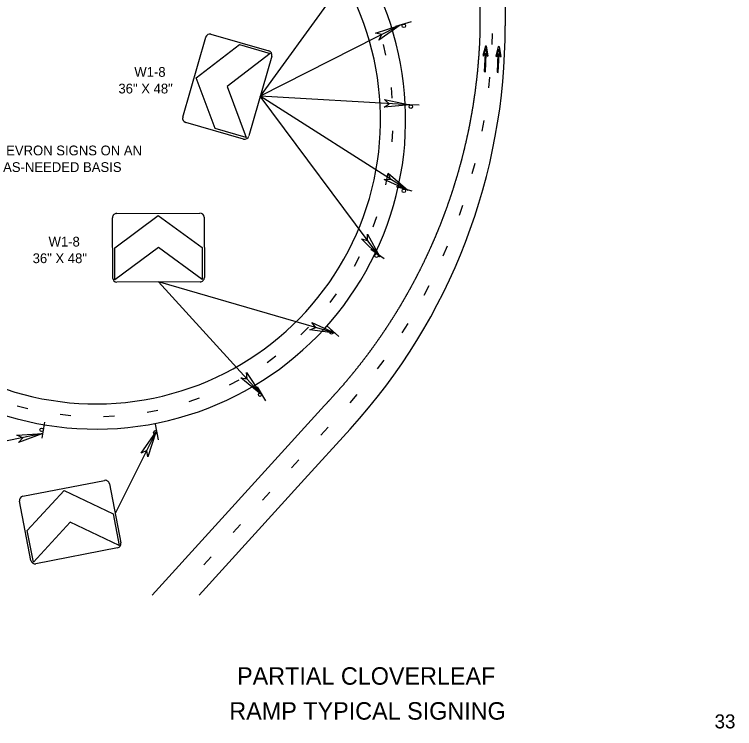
# Model space of a CAD drawing. Extents: x 582908 to 586039, y 1530940 to 1532988.
# Drawn here: x 585008 to 586039, y 1530991 to 1532013 of the extents above; entities that cross this region are included whole.
import ezdxf

# ---------------------------------------------------------------- set-up
doc = ezdxf.new("R2010")
doc.units = 0
for name, color, linetype in [('DirArrowsPavt', 7, 'Continuous'), ('LeaderLine_dp', 7, 'Continuous'), ('PMStripe6W', 7, 'Continuous'), ('PMStripe6W(10-30)', 7, 'Continuous'), ('PMStripe6Y', 7, 'Continuous'), ('SignPanel', 7, 'Continuous'), ('SignSupport', 7, 'Continuous'), ('TextLabel', 7, 'Continuous'), ('TextMisc', 7, 'Continuous'), ('TextShtNo', 7, 'Continuous')]:
    doc.layers.add(name, color=color, linetype=linetype)

# ---------------------------------------------------------------- blocks, each defined once
blk = doc.blocks.new('ArrTermPnt')
at = {"layer": 'LeaderLine_dp'}
for p, q in [((-0.1, 0), (-0.12, 0.02)), ((-0.12, 0.02), (0, 0)), ((0, 0), (-0.12, -0.02)), ((-0.12, -0.02), (-0.1, 0))]:
    blk.add_line(p, q, dxfattribs=at)

msp = doc.modelspace()

# ---------------------------------------------------------------- linework, layer by layer
at = {"layer": 'DirArrowsPavt'}
for p, q in [((585682.8, 1531967.4), (585679.1, 1531953.9)), ((585684.4, 1531967.4), (585682.8, 1531967.4)), ((585686.9, 1531953.5), (585684.4, 1531967.4)), ((585680.6, 1531953.5), (585683.5, 1531963.9)), ((585683.5, 1531963.9), (585685.3, 1531953.2)), ((585701.2, 1531966.6), (585697.5, 1531953)), ((585699, 1531952.6), (585701.9, 1531963)), ((585702.8, 1531966.5), (585701.2, 1531966.6)), ((585701.9, 1531963), (585703.7, 1531952.4)), ((585705.3, 1531952.7), (585702.8, 1531966.5)), ((585679.1, 1531953.9), (585680.6, 1531953.5)), ((585682.3, 1531956.5), (585681.2, 1531930.8)), ((585683.9, 1531956.4), (585682.3, 1531956.5)), ((585682.7, 1531930.7), (585683.9, 1531956.4)), ((585685.3, 1531953.2), (585686.9, 1531953.5)), ((585697.5, 1531953), (585699, 1531952.6)), ((585700.7, 1531955.7), (585699.6, 1531929.9)), ((585702.3, 1531955.6), (585700.7, 1531955.7)), ((585701.1, 1531929.8), (585702.3, 1531955.6)), ((585703.7, 1531952.4), (585705.3, 1531952.7)), ((585681.2, 1531930.8), (585682.7, 1531930.7)), ((585699.6, 1531929.9), (585701.1, 1531929.8))]:
    msp.add_line(p, q, dxfattribs=at)
at = {"layer": 'LeaderLine_dp'}
for p, q in [((585513.2, 1532106.3), (585360.5, 1531895.8)), ((585560.5, 1531997.4), (585360.5, 1531895.8)), ((585525.4, 1531985.7), (585560.5, 1531997.4)), ((585560.5, 1531997.4), (585530.3, 1531975.9)), ((585534.4, 1531984.1), (585525.4, 1531985.7)), ((585530.3, 1531975.9), (585534.4, 1531984.1)), ((585531.5, 1531665.6), (585360.5, 1531895.8)), ((585574.4, 1531883.1), (585360.5, 1531895.8)), ((585571.5, 1531761.3), (585360.5, 1531895.8)), ((585537.6, 1531879.8), (585545.2, 1531884.9)), ((585545.2, 1531884.9), (585538.2, 1531890.8)), ((585538.2, 1531890.8), (585574.4, 1531883.1)), ((585574.4, 1531883.1), (585537.6, 1531879.8)), ((585546.8, 1531777.1), (585543.6, 1531785.6)), ((585543.6, 1531785.6), (585571.5, 1531761.3)), ((585537.7, 1531776.4), (585546.8, 1531777.1)), ((585571.5, 1531761.3), (585537.7, 1531776.4)), ((585531.5, 1531665.6), (585505.3, 1531691.7)), ((585505.3, 1531691.7), (585514.1, 1531689.1)), ((585514.1, 1531689.1), (585514.1, 1531698.3)), ((585514.1, 1531698.3), (585531.5, 1531665.6)), ((585467.9, 1531556.3), (585214.8, 1531629.8)), ((585361.4, 1531469.3), (585214.8, 1531629.8)), ((585439.8, 1531564.4), (585434.3, 1531571.7)), ((585434.3, 1531571.7), (585467.9, 1531556.3)), ((585431.3, 1531561.2), (585439.8, 1531564.4)), ((585467.9, 1531556.3), (585431.3, 1531561.2)), ((585341.7, 1531490.9), (585340.8, 1531500)), ((585340.8, 1531500), (585361.4, 1531469.3)), ((585361.4, 1531469.3), (585332.7, 1531492.6)), ((585332.7, 1531492.6), (585341.7, 1531490.9)), ((585049.1, 1531412.7), (584837.2, 1531369)), ((585012.2, 1531410.7), (585049.1, 1531412.7)), ((585020.5, 1531406.8), (585012.2, 1531410.7)), ((585049.1, 1531412.7), (585014.4, 1531400)), ((585211.1, 1531414.7), (585152.7, 1531298.6)), ((585189.8, 1531384.5), (585211.1, 1531414.7)), ((585211.1, 1531414.7), (585199.6, 1531379.6)), ((585014.4, 1531400), (585020.5, 1531406.8)), ((585198, 1531388.6), (585189.8, 1531384.5)), ((585199.6, 1531379.6), (585198, 1531388.6))]:
    msp.add_line(p, q, dxfattribs=at)
at = {"layer": 'PMStripe6W'}
for p, q in [((585710.3, 1532156.5), (585711, 1531996.2)), ((585489.3, 1531419.3), (585423.8, 1531347.3)), ((585423.8, 1531347.3), (585273.2, 1531181.7))]:
    msp.add_line(p, q, dxfattribs=at)
for centre, radius, start, end in [((585125.6, 1531862.2), 407, 225.0711, 46.1803), ((584859.2, 1531992.4), 851.8, 317.7128, 0.254)]:
    msp.add_arc(centre, radius, start, end, dxfattribs=at)
at = {"layer": 'PMStripe6W(10-30)'}
for p, q in [((585692.3, 1531969.8), (585692.8, 1531985.4)), ((585540.4, 1531954.5), (585536.8, 1531969.7)), ((585687.5, 1531907.5), (585689.2, 1531923)), ((585549.5, 1531892.8), (585548.1, 1531908.3)), ((585678.1, 1531845.7), (585680.9, 1531861.1)), ((585549.4, 1531830.3), (585550.3, 1531845.9)), ((585664, 1531784.8), (585668, 1531799.9)), ((585540.1, 1531768.6), (585543.3, 1531783.9)), ((585645.5, 1531725.2), (585650.5, 1531739.9)), ((585521.9, 1531708.8), (585527.3, 1531723.5)), ((585622.5, 1531667.1), (585628.6, 1531681.4)), ((585495.2, 1531652.4), (585502.6, 1531666.1)), ((585595.2, 1531610.9), (585602.4, 1531624.7)), ((585460.4, 1531600.5), (585469.8, 1531613)), ((585418.5, 1531554.3), (585429.6, 1531565.2)), ((585563.7, 1531556.8), (585572, 1531570.1)), ((585370.2, 1531514.7), (585382.8, 1531523.9)), ((585528.3, 1531505.3), (585537.6, 1531518)), ((585316.6, 1531482.6), (585330.4, 1531489.9)), ((585258.9, 1531458.7), (585273.7, 1531463.9)), ((585489.2, 1531456.6), (585499.3, 1531468.5)), ((585012.6, 1531452.5), (585027.7, 1531448.7)), ((585198.4, 1531443.5), (585213.7, 1531446.5)), ((585073.8, 1531440.4), (585089.4, 1531438.8)), ((585136.2, 1531437.4), (585151.8, 1531438)), ((585447.3, 1531410.3), (585457.8, 1531421.8)), ((585405.4, 1531363.9), (585415.9, 1531375.4)), ((585363.5, 1531317.5), (585374.1, 1531329)), ((585321.7, 1531271.1), (585332.2, 1531282.7)), ((585279.8, 1531224.7), (585290.3, 1531236.3))]:
    msp.add_line(p, q, dxfattribs=at)
at = {"layer": 'PMStripe6Y'}
for p, q in [((585673.5, 1532343.3), (585675, 1531996.1)), ((585452.3, 1531452.9), (585205.7, 1531181.7))]:
    msp.add_line(p, q, dxfattribs=at)
msp.add_arc((585125.6, 1531862.2), 443, 225.021, 46.2304, dxfattribs=at)
for points in [[(585675, 1531996), (585675, 1531994.7), (585675, 1531993.3), (585675, 1531992), (585674.9, 1531990.6), (585674.9, 1531989.2), (585674.9, 1531987.9), (585674.8, 1531986.5), (585674.8, 1531985.1), (585674.7, 1531983.8), (585674.7, 1531982.4), (585674.6, 1531981), (585674.6, 1531979.7), (585674.5, 1531978.3), (585674.5, 1531977), (585674.4, 1531975.6), (585674.3, 1531974.2), (585674.3, 1531972.9), (585674.2, 1531971.5), (585674.1, 1531970.1), (585674.1, 1531968.8), (585674, 1531967.4), (585673.9, 1531966.1), (585673.9, 1531964.7), (585673.8, 1531963.3), (585673.7, 1531962), (585673.6, 1531960.6), (585673.5, 1531959.3), (585673.4, 1531957.9), (585673.3, 1531956.5), (585673.3, 1531955.2), (585673.2, 1531953.8), (585673.1, 1531952.5), (585673, 1531951.1), (585672.9, 1531949.7), (585672.8, 1531948.4), (585672.6, 1531947), (585672.5, 1531945.7), (585672.4, 1531944.3), (585672.3, 1531942.9), (585672.2, 1531941.6), (585672.1, 1531940.2), (585672, 1531938.9), (585671.8, 1531937.5), (585671.7, 1531936.2), (585671.6, 1531934.8), (585671.5, 1531933.4), (585671.3, 1531932.1), (585671.2, 1531930.7), (585671.1, 1531929.4), (585670.9, 1531928), (585670.8, 1531926.7), (585670.6, 1531925.3), (585670.5, 1531924), (585670.3, 1531922.6), (585670.2, 1531921.2), (585670, 1531919.9), (585669.9, 1531918.5), (585669.7, 1531917.2), (585669.6, 1531915.8), (585669.4, 1531914.5), (585669.2, 1531913.1), (585669.1, 1531911.8), (585668.9, 1531910.4), (585668.7, 1531909.1), (585668.6, 1531907.7), (585668.4, 1531906.4), (585668.2, 1531905), (585668, 1531903.7), (585667.9, 1531902.3), (585667.7, 1531901), (585667.5, 1531899.6), (585667.3, 1531898.3), (585667.1, 1531896.9), (585666.9, 1531895.6)], [(585666.9, 1531895.6), (585666.7, 1531894.2), (585666.5, 1531892.9), (585666.3, 1531891.6), (585666.1, 1531890.2), (585665.9, 1531888.9), (585665.7, 1531887.5), (585665.5, 1531886.2), (585665.3, 1531884.8), (585665.1, 1531883.5), (585664.9, 1531882.1), (585664.7, 1531880.8), (585664.4, 1531879.5), (585664.2, 1531878.1), (585664, 1531876.8), (585663.8, 1531875.4), (585663.5, 1531874.1), (585663.3, 1531872.7), (585663.1, 1531871.4), (585662.8, 1531870.1), (585662.6, 1531868.7), (585662.4, 1531867.4), (585662.1, 1531866.1), (585661.9, 1531864.7), (585661.6, 1531863.4), (585661.4, 1531862), (585661.1, 1531860.7), (585660.9, 1531859.4), (585660.6, 1531858), (585660.4, 1531856.7), (585660.1, 1531855.4), (585659.9, 1531854), (585659.6, 1531852.7), (585659.3, 1531851.4), (585659.1, 1531850), (585658.8, 1531848.7), (585658.5, 1531847.4), (585658.2, 1531846), (585658, 1531844.7), (585657.7, 1531843.4), (585657.4, 1531842.1), (585657.1, 1531840.7), (585656.8, 1531839.4), (585656.5, 1531838.1), (585656.3, 1531836.7), (585656, 1531835.4), (585655.7, 1531834.1), (585655.4, 1531832.8), (585655.1, 1531831.4), (585654.8, 1531830.1), (585654.5, 1531828.8), (585654.2, 1531827.5), (585653.8, 1531826.1), (585653.5, 1531824.8), (585653.2, 1531823.5), (585652.9, 1531822.2), (585652.6, 1531820.9), (585652.3, 1531819.5), (585652, 1531818.2), (585651.6, 1531816.9), (585651.3, 1531815.6), (585651, 1531814.3), (585650.6, 1531812.9), (585650.3, 1531811.6), (585650, 1531810.3), (585649.6, 1531809), (585649.3, 1531807.7), (585649, 1531806.4), (585648.6, 1531805.1), (585648.3, 1531803.7), (585647.9, 1531802.4), (585647.6, 1531801.1), (585647.2, 1531799.8), (585646.9, 1531798.5), (585646.5, 1531797.2)], [(585646.5, 1531797.2), (585646.2, 1531795.9), (585645.8, 1531794.6), (585645.4, 1531793.3), (585645.1, 1531792), (585644.7, 1531790.7), (585644.3, 1531789.4), (585644, 1531788), (585643.6, 1531786.7), (585643.2, 1531785.4), (585642.8, 1531784.1), (585642.5, 1531782.8), (585642.1, 1531781.5), (585641.7, 1531780.2), (585641.3, 1531778.9), (585640.9, 1531777.6), (585640.5, 1531776.3), (585640.1, 1531775), (585639.7, 1531773.7), (585639.3, 1531772.4), (585638.9, 1531771.1), (585638.5, 1531769.9), (585638.1, 1531768.6), (585637.7, 1531767.3), (585637.3, 1531766), (585636.9, 1531764.7), (585636.5, 1531763.4), (585636.1, 1531762.1), (585635.7, 1531760.8), (585635.2, 1531759.5), (585634.8, 1531758.2), (585634.4, 1531756.9), (585634, 1531755.7), (585633.6, 1531754.4), (585633.1, 1531753.1), (585632.7, 1531751.8), (585632.3, 1531750.5), (585631.8, 1531749.2), (585631.4, 1531748), (585630.9, 1531746.7), (585630.5, 1531745.4), (585630.1, 1531744.1), (585629.6, 1531742.8), (585629.2, 1531741.6), (585628.7, 1531740.3), (585628.3, 1531739), (585627.8, 1531737.7), (585627.3, 1531736.4), (585626.9, 1531735.2), (585626.4, 1531733.9), (585626, 1531732.6), (585625.5, 1531731.4), (585625, 1531730.1), (585624.6, 1531728.8), (585624.1, 1531727.5), (585623.6, 1531726.3), (585623.1, 1531725), (585622.7, 1531723.7), (585622.2, 1531722.5), (585621.7, 1531721.2), (585621.2, 1531719.9), (585620.7, 1531718.7), (585620.2, 1531717.4), (585619.7, 1531716.2), (585619.3, 1531714.9), (585618.8, 1531713.6), (585618.3, 1531712.4), (585617.8, 1531711.1), (585617.3, 1531709.9), (585616.8, 1531708.6), (585616.3, 1531707.4), (585615.7, 1531706.1), (585615.2, 1531704.8), (585614.7, 1531703.6), (585614.2, 1531702.3)], [(585614.2, 1531702.3), (585613.7, 1531701.1), (585613.2, 1531699.8), (585612.7, 1531698.6), (585612.1, 1531697.3), (585611.6, 1531696.1), (585611.1, 1531694.9), (585610.6, 1531693.6), (585610, 1531692.4), (585609.5, 1531691.1), (585609, 1531689.9), (585608.4, 1531688.6), (585607.9, 1531687.4), (585607.3, 1531686.2), (585606.8, 1531684.9), (585606.3, 1531683.7), (585605.7, 1531682.4), (585605.2, 1531681.2), (585604.6, 1531680), (585604.1, 1531678.7), (585603.5, 1531677.5), (585602.9, 1531676.3), (585602.4, 1531675), (585601.8, 1531673.8), (585601.3, 1531672.6), (585600.7, 1531671.4), (585600.1, 1531670.1), (585599.6, 1531668.9), (585599, 1531667.7), (585598.4, 1531666.5), (585597.8, 1531665.2), (585597.3, 1531664), (585596.7, 1531662.8), (585596.1, 1531661.6), (585595.5, 1531660.3), (585594.9, 1531659.1), (585594.4, 1531657.9), (585593.8, 1531656.7), (585593.2, 1531655.5), (585592.6, 1531654.3), (585592, 1531653.1), (585591.4, 1531651.8), (585590.8, 1531650.6), (585590.2, 1531649.4), (585589.6, 1531648.2), (585589, 1531647), (585588.4, 1531645.8), (585587.8, 1531644.6), (585587.1, 1531643.4), (585586.5, 1531642.2), (585585.9, 1531641), (585585.3, 1531639.8), (585584.7, 1531638.6), (585584.1, 1531637.4), (585583.4, 1531636.2), (585582.8, 1531635), (585582.2, 1531633.8), (585581.6, 1531632.6), (585580.9, 1531631.4), (585580.3, 1531630.2), (585579.7, 1531629), (585579, 1531627.8), (585578.4, 1531626.6), (585577.7, 1531625.5), (585577.1, 1531624.3), (585576.5, 1531623.1), (585575.8, 1531621.9), (585575.2, 1531620.7), (585574.5, 1531619.5), (585573.9, 1531618.4), (585573.2, 1531617.2), (585572.5, 1531616), (585571.9, 1531614.8), (585571.2, 1531613.6), (585570.6, 1531612.5)], [(585570.6, 1531612.5), (585569.9, 1531611.3), (585569.2, 1531610.1), (585568.6, 1531608.9), (585567.9, 1531607.8), (585567.2, 1531606.6), (585566.5, 1531605.4), (585565.9, 1531604.3), (585565.2, 1531603.1), (585564.5, 1531601.9), (585563.8, 1531600.8), (585563.1, 1531599.6), (585562.5, 1531598.5), (585561.8, 1531597.3), (585561.1, 1531596.1), (585560.4, 1531595), (585559.7, 1531593.8), (585559, 1531592.7), (585558.3, 1531591.5), (585557.6, 1531590.4), (585556.9, 1531589.2), (585556.2, 1531588.1), (585555.5, 1531586.9), (585554.8, 1531585.8), (585554.1, 1531584.6), (585553.4, 1531583.5), (585552.7, 1531582.3), (585552, 1531581.2), (585551.2, 1531580), (585550.5, 1531578.9), (585549.8, 1531577.8), (585549.1, 1531576.6), (585548.4, 1531575.5), (585547.6, 1531574.4), (585546.9, 1531573.2), (585546.2, 1531572.1), (585545.4, 1531571), (585544.7, 1531569.8), (585544, 1531568.7), (585543.2, 1531567.6), (585542.5, 1531566.4), (585541.8, 1531565.3), (585541, 1531564.2), (585540.3, 1531563.1), (585539.5, 1531561.9), (585538.8, 1531560.8), (585538, 1531559.7), (585537.3, 1531558.6), (585536.5, 1531557.5), (585535.8, 1531556.4), (585535, 1531555.2), (585534.3, 1531554.1), (585533.5, 1531553), (585532.7, 1531551.9), (585532, 1531550.8), (585531.2, 1531549.7), (585530.4, 1531548.6), (585529.7, 1531547.5), (585528.9, 1531546.4), (585528.1, 1531545.3), (585527.3, 1531544.2), (585526.6, 1531543.1), (585525.8, 1531542), (585525, 1531540.9), (585524.2, 1531539.8), (585523.4, 1531538.7), (585522.7, 1531537.6), (585521.9, 1531536.5), (585521.1, 1531535.4), (585520.3, 1531534.3), (585519.5, 1531533.2), (585518.7, 1531532.2), (585517.9, 1531531.1), (585517.1, 1531530), (585516.3, 1531528.9)], [(585516.3, 1531528.9), (585515.5, 1531527.8), (585514.7, 1531526.8), (585513.9, 1531525.7), (585513.1, 1531524.6), (585512.3, 1531523.5), (585511.5, 1531522.5), (585510.7, 1531521.4), (585509.8, 1531520.3), (585509, 1531519.2), (585508.2, 1531518.2), (585507.4, 1531517.1), (585506.6, 1531516), (585505.7, 1531515), (585504.9, 1531513.9), (585504.1, 1531512.9), (585503.3, 1531511.8), (585502.4, 1531510.7), (585501.6, 1531509.7), (585500.8, 1531508.6), (585499.9, 1531507.6), (585499.1, 1531506.5), (585498.3, 1531505.5), (585497.4, 1531504.4), (585496.6, 1531503.4), (585495.7, 1531502.3), (585494.9, 1531501.3), (585494, 1531500.3), (585493.2, 1531499.2), (585492.3, 1531498.2), (585491.5, 1531497.1), (585490.6, 1531496.1), (585489.8, 1531495.1), (585488.9, 1531494), (585488.1, 1531493), (585487.2, 1531492), (585486.3, 1531490.9), (585485.5, 1531489.9), (585484.6, 1531488.9), (585483.7, 1531487.8), (585482.9, 1531486.8), (585482, 1531485.8), (585481.1, 1531484.8), (585480.3, 1531483.8), (585479.4, 1531482.7), (585478.5, 1531481.7), (585477.6, 1531480.7), (585476.7, 1531479.7), (585475.9, 1531478.7), (585475, 1531477.7), (585474.1, 1531476.7), (585473.2, 1531475.7), (585472.3, 1531474.7), (585471.4, 1531473.7), (585470.5, 1531472.7), (585469.6, 1531471.6), (585468.7, 1531470.7), (585467.8, 1531469.7), (585466.9, 1531468.7), (585466, 1531467.7), (585465.1, 1531466.7), (585464.2, 1531465.7), (585463.3, 1531464.7), (585462.4, 1531463.7), (585461.5, 1531462.7), (585460.6, 1531461.7), (585459.7, 1531460.7), (585458.8, 1531459.8), (585457.9, 1531458.8), (585456.9, 1531457.8), (585456, 1531456.8), (585455.1, 1531455.8), (585454.2, 1531454.9), (585452.3, 1531452.9)]]:
    msp.add_spline(points, degree=3, dxfattribs=at)
at = {"layer": 'SignPanel'}
for p, q in [((585268.9, 1531922.1), (585330.5, 1531969.5)), ((585330.5, 1531969.5), (585374.8, 1531956.8)), ((585374.8, 1531956.8), (585313.2, 1531909.4)), ((585296, 1531849.3), (585268.9, 1531922.1)), ((585313.2, 1531909.4), (585340.3, 1531836.5)), ((585340.3, 1531836.5), (585296, 1531849.3)), ((585152.1, 1531678.7), (585214.5, 1531725.1)), ((585214.5, 1531725.1), (585277.2, 1531679.2)), ((585152.3, 1531632.6), (585152.1, 1531678.7)), ((585214.6, 1531679), (585152.3, 1531632.6)), ((585277.4, 1531633.1), (585214.6, 1531679)), ((585277.2, 1531679.2), (585277.4, 1531633.1)), ((585026.9, 1531274.1), (585079.5, 1531331.3)), ((585079.5, 1531331.3), (585149.7, 1531298)), ((585149.7, 1531298), (585158.5, 1531252.7)), ((585088.3, 1531286), (585035.7, 1531228.8)), ((585158.5, 1531252.7), (585088.3, 1531286)), ((585035.7, 1531228.8), (585026.9, 1531274.1))]:
    msp.add_line(p, q, dxfattribs=at)
for points in [[(585249.5, 1531865.8), (585282.3, 1531980.1)], [(585289.9, 1531984.3), (585372.7, 1531960.6)], [(585376.9, 1531953), (585344.1, 1531838.7)], [(585336.5, 1531834.4), (585253.7, 1531858.2)], [(585149.2, 1531635.7), (585148.9, 1531721.8)], [(585155, 1531728), (585273.9, 1531728.4)], [(585280.1, 1531722.3), (585280.4, 1531636.1)], [(585274.3, 1531630), (585155.3, 1531629.5)], [(585020.5, 1531323), (585137.3, 1531345.7)], [(585144.5, 1531340.8), (585160.9, 1531256.3)], [(585032.1, 1531231.2), (585015.7, 1531315.8)], [(585156.1, 1531249.1), (585039.3, 1531226.4)]]:
    msp.add_lwpolyline(points, dxfattribs=at)
for centre, start, end in [((585288.2, 1531978.4), 74.0069, 164.0069), ((585371, 1531954.7), 344.0069, 74.0069), ((585255.4, 1531864.1), 164.0069, 254.0069), ((585338.2, 1531840.3), 254.0069, 344.0069), ((585155, 1531721.8), 90.2084, 180.2084), ((585274, 1531722.3), 0.2084, 90.2084), ((585155.3, 1531635.7), 180.2084, 270.2084), ((585274.3, 1531636.1), 270.2084, 0.2084), ((585138.5, 1531339.7), 10.9993, 100.9993), ((585021.7, 1531317), 100.9993, 190.9993), ((585154.9, 1531255.1), 280.9993, 10.9993), ((585038.1, 1531232.4), 190.9993, 280.9993)]:
    msp.add_arc(centre, 6.15, start, end, dxfattribs=at)
at = {"layer": 'SignSupport'}
for p, q in [((585576.5, 1532001.9), (585554.1, 1531995.6)), ((585587.7, 1531882.8), (585564.5, 1531883.4)), ((585577.9, 1531759.5), (585555.5, 1531765.8)), ((585537.9, 1531663.1), (585518.5, 1531676.1)), ((585472.9, 1531551.8), (585455.5, 1531567.4)), ((585368.3, 1531459.8), (585356.3, 1531479.8)), ((585048, 1531406.2), (585051.9, 1531429.1)), ((585214.7, 1531403.6), (585210.3, 1531426.4))]:
    msp.add_line(p, q, dxfattribs=at)
for centre in [(585565.9, 1531996.3), (585576, 1531880.6), (585566, 1531760.3), (585526.8, 1531667.5), (585462.5, 1531557.7), (585360.2, 1531468.5), (585047.5, 1531418.1), (585210.1, 1531414.5)]:
    msp.add_circle(centre, 2.49, dxfattribs=at)

# ---------------------------------------------------------------- block references
at = {"layer": 'TextLabel'}
for p, xscale, yscale, rotation in [((585560.5, 1531997.4), 2.0416666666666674, 1.9442318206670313, 26.925427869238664), ((585467.9, 1531556.3), 2.041666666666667, 1.9442318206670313, -16.189425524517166), ((585361.4, 1531469.3), 2.0416666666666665, 1.9442318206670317, -47.59235154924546), ((585049.1, 1531412.7), 2.041666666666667, 1.9442318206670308, 11.660681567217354), ((585211.1, 1531414.7), 2.041666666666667, 1.9442318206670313, 63.3113532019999)]:
    msp.add_blockref('ArrTermPnt', p, dxfattribs=dict(at, xscale=xscale, yscale=yscale, rotation=rotation))

# ---------------------------------------------------------------- texts
for s, p in [('W1-8', (585180.2, 1531923.4)), ('36" X 48"', (585157.4, 1531899.6)), ('CHEVRON SIGNS ON AN', (584969.6, 1531811)), ('AS-NEEDED BASIS', (584992.3, 1531787.2)), ('W1-8', (585057.4, 1531680.5)), ('36" X 48"', (585034.6, 1531656.7))]:
    msp.add_text(s, height=14, dxfattribs=at).set_placement(p)
at = {"layer": 'TextMisc'}
for s, p in [('   PARTIAL CLOVERLEAF   ', (585299.4, 1531053.3)), ('  RAMP TYPICAL SIGNING  ', (585297.6, 1531003.3))]:
    msp.add_text(s, height=25, rotation=360, dxfattribs=at).set_placement(p)
at = {"layer": 'TextShtNo'}
msp.add_text('33', height=20, rotation=360, dxfattribs=at).set_placement((586010.9, 1530990.8))

doc.saveas('drawing.dxf')
